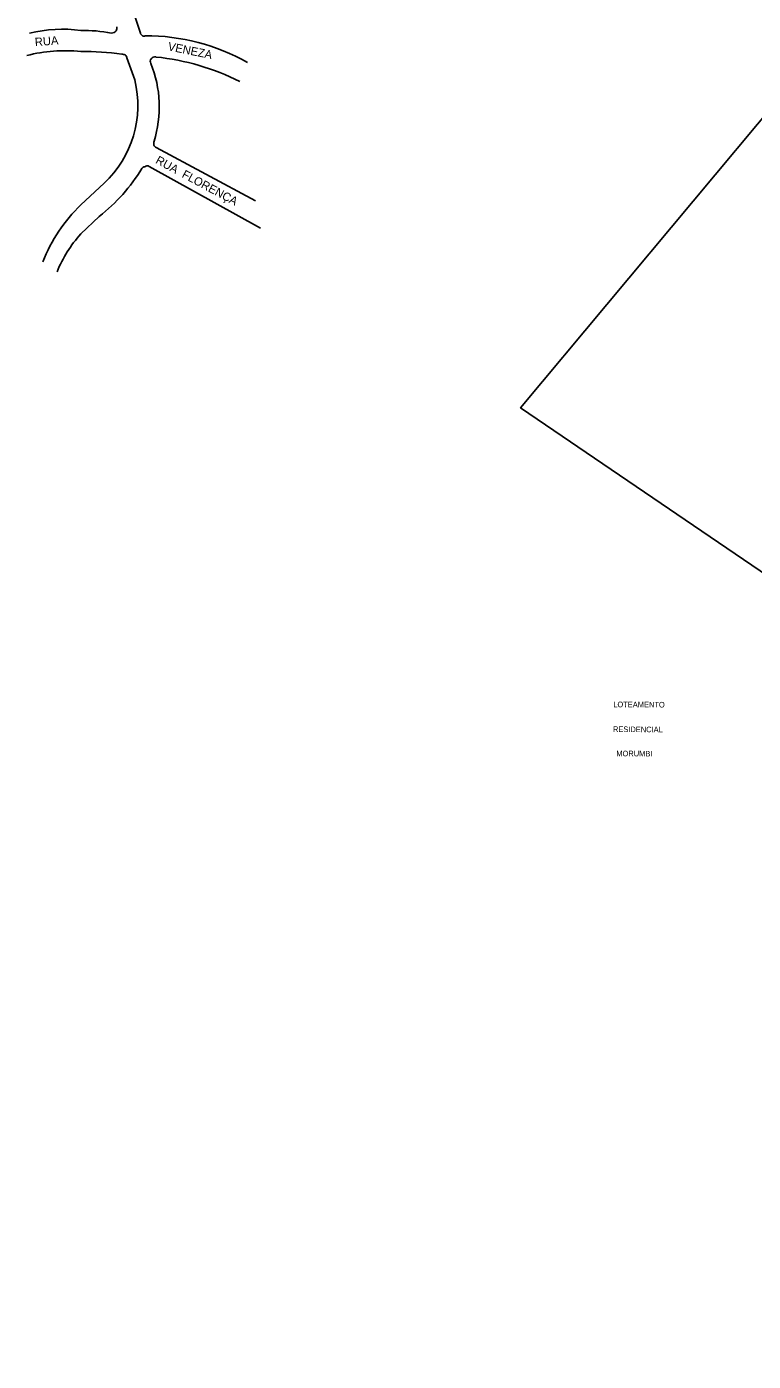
# Model space of a CAD drawing. Extents: x 325709 to 364434, y 7573432 to 7597073.
# Drawn here: x 336043 to 336563, y 7587333 to 7588289 of the extents above; entities that cross this region are included whole.
import ezdxf

# ---------------------------------------------------------------- set-up
doc = ezdxf.new("R2010")
doc.units = 0
for name, color, linetype in [('EDIFIDENTIF', 7, 'Continuous'), ('LIMITE_BAIRROS_MUNICIPIOS', 7, 'Continuous'), ('LOGRADOURO', 7, 'Continuous'), ('LOGRADOURO_TEXTO', 7, 'Continuous')]:
    doc.layers.add(name, color=color, linetype=linetype)

msp = doc.modelspace()

# ---------------------------------------------------------------- linework, layer by layer
at = {"layer": 'LIMITE_BAIRROS_MUNICIPIOS'}
msp.add_lwpolyline([(337342.22, 7587372.39), (336396.46, 7588016.13), (336582.01, 7588238.23), (337316, 7588174.16), (337422.07, 7588277), (337411.03, 7588347.71), (337527.32, 7588375.68), (337546.84, 7588303.24), (337603.06, 7588272.31), (337684.9, 7588124.18), (337619.52, 7587978.17), (337693.23, 7587913.48), (337760.4, 7588085.1), (337859.79, 7588021.24), (337525.43, 7587332.74), (337420.34, 7587429.62), (337342.22, 7587372.39)], dxfattribs=at)
at = {"layer": 'LOGRADOURO'}
for p, q in [((336124.03, 7588285.31), (336081.39, 7588412.6)), ((336114.45, 7588266.87), (336119.99, 7588251.04)), ((336206.5, 7588164.51), (336135.41, 7588202.77)), ((336130.34, 7588189.09), (336210.21, 7588144.89)), ((336098.03, 7588177.07), (336081.39, 7588161.55)), ((336081.39, 7588140.74), (336094.66, 7588153.27))]:
    msp.add_line(p, q, dxfattribs=at)
for centre, radius, start, end in [((336103.17, 7588288.27), 4.06, 331.34102, 13.85229), ((336067.8, 7588195.17), 92.28, 81.52879, 104.52318), ((336084.52, 7588192.61), 93.88, 78.44914, 91.90683), ((336102.91, 7588289.64), 5.07, 274.58322, 318.98223), ((336126.27, 7588285.08), 2.25, 173.968, 240.34943), ((336126.54, 7588284.39), 1.88, 222.52503, 302.00024), ((336127.53, 7588133.11), 149.69, 60.70724, 89.99699), ((336070.27, 7588160.6), 111.46, 84.274, 104.34665), ((336082.08, 7588049), 222.5, 82.58485, 90.17631), ((336108.44, 7588254.26), 15.56, 72.6928, 81.32486), ((336110.87, 7588266.21), 3.64, 10.32505, 52.76099), ((336134.74, 7588264.51), 3.53, 149.57113, 207.80662), ((336053.75, 7588231.71), 83.87, 342.95695, 21.80926), ((336134.62, 7588263.57), 4, 80.69005, 136.96532), ((336117.65, 7588096.43), 171.99, 63.16859, 84.11822), ((336046.44, 7588232.64), 75.82, 312.87139, 14.04875), ((336137.77, 7588205.53), 4.14, 157.35577, 196.46669), ((336135.76, 7588204.73), 2, 190.90458, 259.98946), ((336011.88, 7588257.83), 133.37, 308.36728, 328.19899), ((336126.91, 7588187.12), 1.74, 78.96505, 165.80034), ((336128.91, 7588187.5), 2.14, 48.012, 141.36743), ((336163.13, 7588077.4), 117.31, 134.16576, 158.27224), ((336152.4, 7588077.29), 95.23, 138.21562, 157.58676)]:
    msp.add_arc(centre, radius, start, end, dxfattribs=at)

# ---------------------------------------------------------------- texts
at = {"layer": 'EDIFIDENTIF'}
for s, p in [('LOTEAMENTO', (336462.82, 7587801.54)), ('RESIDENCIAL', (336462.61, 7587783.76)), ('MORUMBI', (336464.99, 7587766.38))]:
    msp.add_text(s, height=4, rotation=359.63581, dxfattribs=at).set_placement(p)
at = {"layer": 'LOGRADOURO_TEXTO'}
for s, rotation, p in [('RUA', 4.43002, (336048.67, 7588275.23)), ('VENEZA', 348.49325, (336143.43, 7588272.39)), ('RUA  FLORENÇA', 331.71443, (336134.42, 7588191.72))]:
    msp.add_text(s, height=6, rotation=rotation, dxfattribs=at).set_placement(p)

doc.saveas('drawing.dxf')
